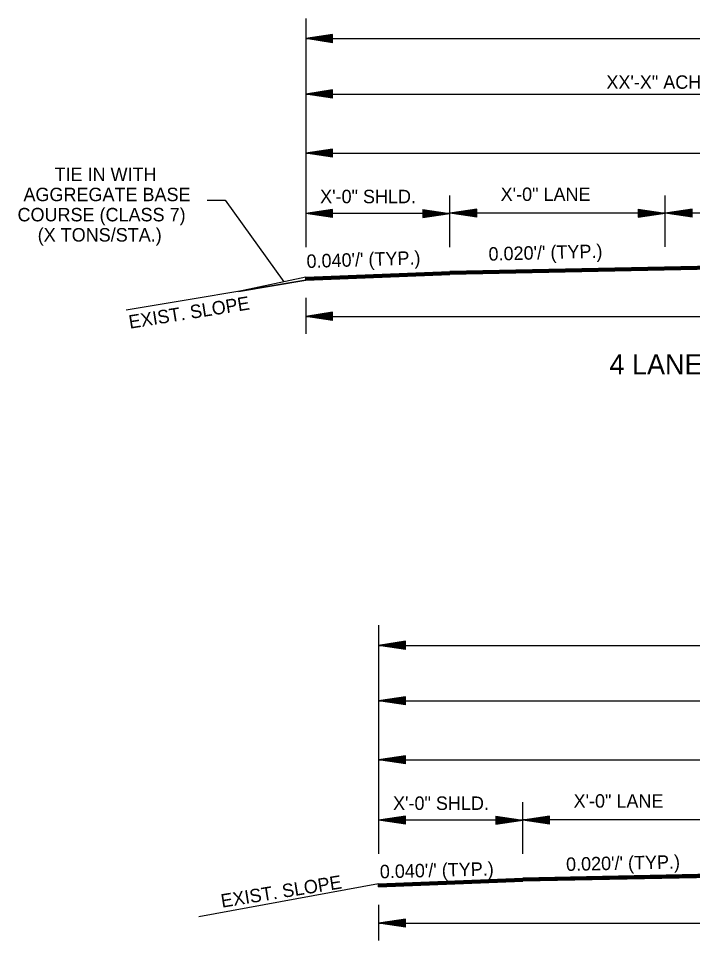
# Model space of a CAD drawing. Extents: x 544199 to 1930787, y -1968972 to 596640.
# Drawn here: x 551425 to 551801, y -1962384 to -1961870 of the extents above; entities that cross this region are included whole.
import ezdxf

# ---------------------------------------------------------------- set-up
doc = ezdxf.new("R2010")
doc.units = 0
doc.layers.add('R_Draft', color=7, linetype='Continuous')

msp = doc.modelspace()

# ---------------------------------------------------------------- linework, layer by layer
at = {"layer": 'R_Draft'}
for p, q in [((551585.29, -1961869.55), (551585.29, -1961996.98)), ((551600.29, -1961878.56), (551585.29, -1961880.81)), ((551585.29, -1961880.81), (552225.74, -1961880.81)), ((551600.29, -1961883.06), (551585.29, -1961880.81)), ((551600.29, -1961878.94), (551587.8, -1961880.81)), ((551600.29, -1961882.69), (551587.8, -1961880.81)), ((551600.29, -1961879.32), (551590.38, -1961880.81)), ((551600.29, -1961882.31), (551590.38, -1961880.81)), ((551600.29, -1961879.7), (551592.88, -1961880.81)), ((551600.29, -1961881.93), (551592.88, -1961880.81)), ((551600.29, -1961880.08), (551595.42, -1961880.81)), ((551600.29, -1961881.54), (551595.42, -1961880.81)), ((551600.29, -1961880.46), (551597.92, -1961880.81)), ((551600.29, -1961881.17), (551597.92, -1961880.81)), ((551600.29, -1961883.06), (551600.29, -1961878.56)), ((551600.29, -1961909.43), (551585.29, -1961911.68)), ((551585.29, -1961911.68), (552225.74, -1961911.68)), ((551600.29, -1961913.93), (551585.29, -1961911.68)), ((551600.29, -1961909.81), (551587.8, -1961911.68)), ((551600.29, -1961913.56), (551587.8, -1961911.68)), ((551600.29, -1961910.19), (551590.38, -1961911.68)), ((551600.29, -1961913.18), (551590.38, -1961911.68)), ((551600.29, -1961910.57), (551592.88, -1961911.68)), ((551600.29, -1961912.8), (551592.88, -1961911.68)), ((551600.29, -1961910.95), (551595.42, -1961911.68)), ((551600.29, -1961912.41), (551595.42, -1961911.68)), ((551600.29, -1961911.33), (551597.92, -1961911.68)), ((551600.29, -1961912.04), (551597.92, -1961911.68)), ((551600.29, -1961913.93), (551600.29, -1961909.43)), ((551600.29, -1961942.36), (551585.29, -1961944.61)), ((551600.29, -1961942.74), (551587.8, -1961944.61)), ((551600.29, -1961946.86), (551600.29, -1961942.36)), ((551585.29, -1961944.61), (552225.74, -1961944.61)), ((551600.29, -1961946.86), (551585.29, -1961944.61)), ((551600.29, -1961946.49), (551587.8, -1961944.61)), ((551600.29, -1961943.12), (551590.38, -1961944.61)), ((551600.29, -1961946.1), (551590.38, -1961944.61)), ((551600.29, -1961943.49), (551592.88, -1961944.61)), ((551600.29, -1961945.73), (551592.88, -1961944.61)), ((551600.29, -1961943.88), (551595.42, -1961944.61)), ((551600.29, -1961945.34), (551595.42, -1961944.61)), ((551600.29, -1961944.26), (551597.92, -1961944.61)), ((551600.29, -1961944.96), (551597.92, -1961944.61)), ((551665.55, -1961996.81), (551665.55, -1961968.26)), ((551665.55, -1961996.98), (551665.55, -1961968.26)), ((551785.55, -1961996.81), (551785.55, -1961968.26)), ((551600.29, -1961976.07), (551585.29, -1961978.32)), ((551665.55, -1961978.32), (551585.29, -1961978.32)), ((551600.29, -1961980.57), (551585.29, -1961978.32)), ((551600.29, -1961976.44), (551587.8, -1961978.32)), ((551600.29, -1961980.19), (551587.8, -1961978.32)), ((551600.29, -1961976.83), (551590.38, -1961978.32)), ((551600.29, -1961979.81), (551590.38, -1961978.32)), ((551600.29, -1961977.2), (551592.88, -1961978.32)), ((551600.29, -1961979.44), (551592.88, -1961978.32)), ((551600.29, -1961977.58), (551595.42, -1961978.32)), ((551600.29, -1961979.05), (551595.42, -1961978.32)), ((551600.29, -1961977.97), (551597.92, -1961978.32)), ((551600.29, -1961978.67), (551597.92, -1961978.32)), ((551600.29, -1961980.57), (551600.29, -1961976.07)), ((551650.55, -1961976.07), (551665.55, -1961978.32)), ((551650.55, -1961976.07), (551650.55, -1961980.57)), ((551650.55, -1961976.44), (551663.05, -1961978.32)), ((551650.55, -1961976.83), (551660.47, -1961978.32)), ((551650.55, -1961977.2), (551657.97, -1961978.32)), ((551650.55, -1961977.59), (551655.43, -1961978.32)), ((551650.55, -1961977.97), (551652.92, -1961978.32)), ((551650.55, -1961980.57), (551665.55, -1961978.32)), ((551650.55, -1961979.05), (551655.43, -1961978.32)), ((551650.55, -1961979.81), (551660.47, -1961978.32)), ((551650.55, -1961980.19), (551663.05, -1961978.32)), ((551650.55, -1961979.44), (551657.97, -1961978.32)), ((551650.55, -1961978.67), (551652.92, -1961978.32)), ((551680.55, -1961975.9), (551665.55, -1961978.15)), ((551785.55, -1961978.15), (551665.55, -1961978.15)), ((551680.55, -1961980.4), (551665.55, -1961978.15)), ((551680.55, -1961976.27), (551668.06, -1961978.15)), ((551680.55, -1961980.02), (551668.06, -1961978.15)), ((551680.55, -1961976.66), (551670.64, -1961978.15)), ((551680.55, -1961979.64), (551670.64, -1961978.15)), ((551680.55, -1961977.03), (551673.14, -1961978.15)), ((551680.55, -1961979.27), (551673.14, -1961978.15)), ((551680.55, -1961977.41), (551675.68, -1961978.15)), ((551680.55, -1961978.88), (551675.68, -1961978.15)), ((551680.55, -1961977.8), (551678.18, -1961978.15)), ((551680.55, -1961978.5), (551678.18, -1961978.15)), ((551680.55, -1961980.4), (551680.55, -1961975.9)), ((551770.55, -1961975.9), (551785.55, -1961978.15)), ((551770.55, -1961975.9), (551770.55, -1961980.4)), ((551770.55, -1961976.27), (551783.05, -1961978.15)), ((551770.55, -1961976.66), (551780.47, -1961978.15)), ((551770.55, -1961977.03), (551777.97, -1961978.15)), ((551770.55, -1961977.42), (551775.43, -1961978.15)), ((551770.55, -1961977.8), (551772.92, -1961978.15)), ((551770.55, -1961980.4), (551785.55, -1961978.15)), ((551770.55, -1961978.88), (551775.43, -1961978.15)), ((551770.55, -1961979.64), (551780.47, -1961978.15)), ((551770.55, -1961980.02), (551783.05, -1961978.15)), ((551770.55, -1961979.27), (551777.97, -1961978.15)), ((551770.55, -1961978.5), (551772.92, -1961978.15)), ((551800.55, -1961975.9), (551785.55, -1961978.15)), ((551905.48, -1961978.15), (551785.55, -1961978.15)), ((551800.55, -1961980.4), (551785.55, -1961978.15)), ((551800.55, -1961976.27), (551788.06, -1961978.15)), ((551800.55, -1961980.02), (551788.06, -1961978.15)), ((551800.55, -1961976.66), (551790.64, -1961978.15)), ((551800.55, -1961979.64), (551790.64, -1961978.15)), ((551800.55, -1961977.03), (551793.14, -1961978.15)), ((551800.55, -1961979.27), (551793.14, -1961978.15)), ((551800.55, -1961977.41), (551795.68, -1961978.15)), ((551800.55, -1961978.88), (551795.68, -1961978.15)), ((551800.55, -1961977.8), (551798.18, -1961978.15)), ((551800.55, -1961978.5), (551798.18, -1961978.15)), ((551800.55, -1961980.4), (551800.55, -1961975.9)), ((551905.48, -1962005.76), (551665.55, -1962010.55)), ((551905.49, -1962006.05), (551665.56, -1962010.85)), ((551905.49, -1962006.35), (551665.57, -1962011.15)), ((551905.5, -1962006.65), (551665.57, -1962011.45)), ((551905.51, -1962006.95), (551665.58, -1962011.75)), ((551905.51, -1962007.25), (551665.58, -1962012.05)), ((551905.52, -1962007.45), (551665.59, -1962012.25)), ((551585.29, -1962013.76), (551547.8, -1962021.71)), ((551585.29, -1962013.76), (551665.55, -1962010.55)), ((551585.29, -1962014.06), (551665.57, -1962010.85)), ((551585.29, -1962014.36), (551665.58, -1962011.15)), ((551585.29, -1962014.66), (551665.59, -1962011.45)), ((551585.29, -1962014.96), (551665.6, -1962011.75)), ((551585.29, -1962015.27), (551665.61, -1962012.05)), ((551585.29, -1962015.47), (551665.62, -1962012.25)), ((551585.29, -1962015.46), (551585.29, -1962013.76)), ((551585.29, -1962015.46), (551585.29, -1962013.76)), ((551585.29, -1962013.76), (551585.29, -1962015.47)), ((551585.29, -1962015.46), (551485.23, -1962032.14)), ((551547.8, -1962021.71), (551585.29, -1962015.46)), ((551585.29, -1962015.46), (551585.29, -1962015.46)), ((551585.29, -1962025.36), (551585.29, -1962045.36)), ((551600.29, -1962033.36), (551585.29, -1962035.61)), ((551600.29, -1962033.74), (551587.8, -1962035.61)), ((551600.29, -1962034.12), (551590.38, -1962035.61)), ((551600.29, -1962034.5), (551592.88, -1962035.61)), ((551600.29, -1962034.88), (551595.42, -1962035.61)), ((551600.29, -1962035.26), (551597.92, -1962035.61)), ((551600.29, -1962037.86), (551600.29, -1962033.36)), ((551585.29, -1962035.61), (552225.74, -1962035.61)), ((551600.29, -1962037.86), (551585.29, -1962035.61)), ((551600.29, -1962037.49), (551587.8, -1962035.61)), ((551600.29, -1962037.11), (551590.38, -1962035.61)), ((551600.29, -1962036.73), (551592.88, -1962035.61)), ((551600.29, -1962036.34), (551595.42, -1962035.61)), ((551600.29, -1962035.97), (551597.92, -1962035.61)), ((551625.91, -1962207.72), (551625.91, -1962335.15)), ((551640.91, -1962216.73), (551625.91, -1962218.98)), ((551625.91, -1962218.98), (552266.36, -1962218.98)), ((551640.91, -1962221.23), (551625.91, -1962218.98)), ((551640.91, -1962217.11), (551628.42, -1962218.98)), ((551640.91, -1962220.86), (551628.42, -1962218.98)), ((551640.91, -1962217.49), (551631, -1962218.98)), ((551640.91, -1962220.48), (551631, -1962218.98)), ((551640.91, -1962217.87), (551633.49, -1962218.98)), ((551640.91, -1962220.1), (551633.49, -1962218.98)), ((551640.91, -1962218.25), (551636.04, -1962218.98)), ((551640.91, -1962219.71), (551636.04, -1962218.98)), ((551640.91, -1962218.63), (551638.54, -1962218.98)), ((551640.91, -1962219.34), (551638.54, -1962218.98)), ((551640.91, -1962221.23), (551640.91, -1962216.73)), ((551640.91, -1962247.6), (551625.91, -1962249.85)), ((551625.91, -1962249.85), (552266.36, -1962249.85)), ((551640.91, -1962252.1), (551625.91, -1962249.85)), ((551640.91, -1962247.98), (551628.42, -1962249.85)), ((551640.91, -1962251.73), (551628.42, -1962249.85)), ((551640.91, -1962248.36), (551631, -1962249.85)), ((551640.91, -1962251.35), (551631, -1962249.85)), ((551640.91, -1962248.74), (551633.49, -1962249.85)), ((551640.91, -1962250.97), (551633.49, -1962249.85)), ((551640.91, -1962249.12), (551636.04, -1962249.85)), ((551640.91, -1962250.58), (551636.04, -1962249.85)), ((551640.91, -1962249.5), (551638.54, -1962249.85)), ((551640.91, -1962250.21), (551638.54, -1962249.85)), ((551640.91, -1962252.1), (551640.91, -1962247.6)), ((551640.91, -1962280.53), (551625.91, -1962282.78)), ((551640.91, -1962280.91), (551628.42, -1962282.78)), ((551640.91, -1962281.29), (551631, -1962282.78)), ((551640.91, -1962281.67), (551633.49, -1962282.78)), ((551640.91, -1962282.05), (551636.04, -1962282.78)), ((551640.91, -1962285.03), (551640.91, -1962280.53)), ((551625.91, -1962282.78), (552266.36, -1962282.78)), ((551640.91, -1962285.03), (551625.91, -1962282.78)), ((551640.91, -1962284.66), (551628.42, -1962282.78)), ((551640.91, -1962284.28), (551631, -1962282.78)), ((551640.91, -1962283.9), (551633.49, -1962282.78)), ((551640.91, -1962283.51), (551636.04, -1962282.78)), ((551640.91, -1962282.43), (551638.54, -1962282.78)), ((551640.91, -1962283.14), (551638.54, -1962282.78)), ((551706.17, -1962334.98), (551706.17, -1962306.43)), ((551706.17, -1962335.15), (551706.17, -1962306.43)), ((551640.91, -1962314.24), (551625.91, -1962316.49)), ((551706.17, -1962316.49), (551625.91, -1962316.49)), ((551640.91, -1962318.74), (551625.91, -1962316.49)), ((551640.91, -1962314.61), (551628.42, -1962316.49)), ((551640.91, -1962318.36), (551628.42, -1962316.49)), ((551640.91, -1962315), (551631, -1962316.49)), ((551640.91, -1962317.98), (551631, -1962316.49)), ((551640.91, -1962315.37), (551633.49, -1962316.49)), ((551640.91, -1962317.61), (551633.49, -1962316.49)), ((551640.91, -1962315.75), (551636.04, -1962316.49)), ((551640.91, -1962317.22), (551636.04, -1962316.49)), ((551640.91, -1962316.14), (551638.54, -1962316.49)), ((551640.91, -1962316.84), (551638.54, -1962316.49)), ((551640.91, -1962318.74), (551640.91, -1962314.24)), ((551691.17, -1962314.24), (551706.17, -1962316.49)), ((551691.17, -1962314.24), (551691.17, -1962318.74)), ((551691.17, -1962314.61), (551703.67, -1962316.49)), ((551691.17, -1962315), (551701.09, -1962316.49)), ((551691.17, -1962315.37), (551698.59, -1962316.49)), ((551691.17, -1962315.76), (551696.05, -1962316.49)), ((551691.17, -1962316.14), (551693.54, -1962316.49)), ((551691.17, -1962318.74), (551706.17, -1962316.49)), ((551691.17, -1962317.22), (551696.05, -1962316.49)), ((551691.17, -1962317.98), (551701.09, -1962316.49)), ((551691.17, -1962318.36), (551703.67, -1962316.49)), ((551691.17, -1962317.61), (551698.59, -1962316.49)), ((551691.17, -1962316.84), (551693.54, -1962316.49)), ((551721.17, -1962314.24), (551706.17, -1962316.49)), ((551826.17, -1962316.32), (551706.17, -1962316.32)), ((551721.17, -1962318.74), (551706.17, -1962316.49)), ((551721.17, -1962314.61), (551708.68, -1962316.49)), ((551721.17, -1962318.36), (551708.68, -1962316.49)), ((551721.17, -1962315), (551711.26, -1962316.49)), ((551721.17, -1962317.98), (551711.26, -1962316.49)), ((551721.17, -1962315.37), (551713.75, -1962316.49)), ((551721.17, -1962317.61), (551713.75, -1962316.49)), ((551721.17, -1962315.75), (551716.3, -1962316.49)), ((551721.17, -1962317.22), (551716.3, -1962316.49)), ((551721.17, -1962316.14), (551718.8, -1962316.49)), ((551721.17, -1962316.84), (551718.8, -1962316.49)), ((551721.17, -1962318.74), (551721.17, -1962314.24)), ((551625.91, -1962351.93), (551706.17, -1962348.72)), ((551946.1, -1962343.93), (551706.17, -1962348.72)), ((551946.1, -1962344.23), (551706.18, -1962349.02)), ((551946.11, -1962344.53), (551706.18, -1962349.32)), ((551946.12, -1962344.83), (551706.19, -1962349.62)), ((551946.12, -1962345.13), (551706.2, -1962349.92)), ((551946.13, -1962345.43), (551706.2, -1962350.22)), ((551946.13, -1962345.63), (551706.21, -1962350.42)), ((551625.91, -1962351.93), (551525.84, -1962370.31)), ((551625.91, -1962352.24), (551706.18, -1962349.02)), ((551625.91, -1962352.54), (551706.2, -1962349.32)), ((551625.91, -1962352.84), (551706.21, -1962349.62)), ((551625.91, -1962353.14), (551706.22, -1962349.92)), ((551625.91, -1962353.44), (551706.23, -1962350.22)), ((551625.91, -1962353.64), (551706.24, -1962350.42)), ((551625.91, -1962353.63), (551625.91, -1962351.93)), ((551625.91, -1962351.93), (551625.91, -1962353.64)), ((551625.91, -1962363.54), (551625.91, -1962383.54)), ((551640.91, -1962371.53), (551625.91, -1962373.78)), ((551625.91, -1962373.78), (552266.36, -1962373.78)), ((551640.91, -1962376.03), (551625.91, -1962373.78)), ((551640.91, -1962371.91), (551628.42, -1962373.78)), ((551640.91, -1962375.66), (551628.42, -1962373.78)), ((551640.91, -1962372.29), (551631, -1962373.78)), ((551640.91, -1962375.28), (551631, -1962373.78)), ((551640.91, -1962372.67), (551633.49, -1962373.78)), ((551640.91, -1962374.9), (551633.49, -1962373.78)), ((551640.91, -1962373.05), (551636.04, -1962373.78)), ((551640.91, -1962374.51), (551636.04, -1962373.78)), ((551640.91, -1962373.43), (551638.54, -1962373.78)), ((551640.91, -1962374.14), (551638.54, -1962373.78)), ((551640.91, -1962376.03), (551640.91, -1962371.53))]:
    msp.add_line(p, q, dxfattribs=at)
msp.add_lwpolyline([(551530.45, -1961970.87), (551540.45, -1961970.87), (551573.1, -1962016.35)], dxfattribs=at)

# ---------------------------------------------------------------- texts
for s, height, p in [('XX\'-X" ACHM SURFACE COURSE (1/2") FOR LEVELING *', 7.5, (551752.81, -1961908.78)), ('TIE IN WITH ', 7.5, (551445.37, -1961960.16)), ('AGGREGATE BASE', 7.5, (551428.06, -1961971.41)), ('X\'-0" SHLD.', 7.5, (551593.33, -1961972.55)), ('X\'-0" LANE', 7.5, (551693.9, -1961971.29)), ('COURSE (CLASS 7)', 7.5, (551424.75, -1961982.66)), ('(X TONS/STA.)', 7.5, (551435.98, -1961993.91)), ('4 LANE OPEN SHOULDER OVERLAY', 11.25, (551754.53, -1962067.98)), ('X\'-0" LANE', 7.5, (551734.51, -1962309.46)), ('X\'-0" SHLD.', 7.5, (551633.95, -1962310.72))]:
    msp.add_text(s, height=height, dxfattribs=at).set_placement(p)
for s, rotation, p in [("0.040'/' (TYP.)", 1.8576, (551585.87, -1962008.66)), ("0.020'/' (TYP.)", 1.5359, (551687.24, -1962004.61)), ('EXIST. SLOPE', 9.1534, (551487.33, -1962042.53)), ("0.020'/' (TYP.)", 1.2821, (551730.42, -1962344.76)), ("0.040'/' (TYP.)", 1.5089, (551626.68, -1962348.88)), ('EXIST. SLOPE', 9.1534, (551538.66, -1962365.24))]:
    msp.add_text(s, height=7.5, rotation=rotation, dxfattribs=at).set_placement(p)

doc.saveas('drawing.dxf')
